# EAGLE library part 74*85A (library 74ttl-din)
4-bit Magnitude COMPARATOR
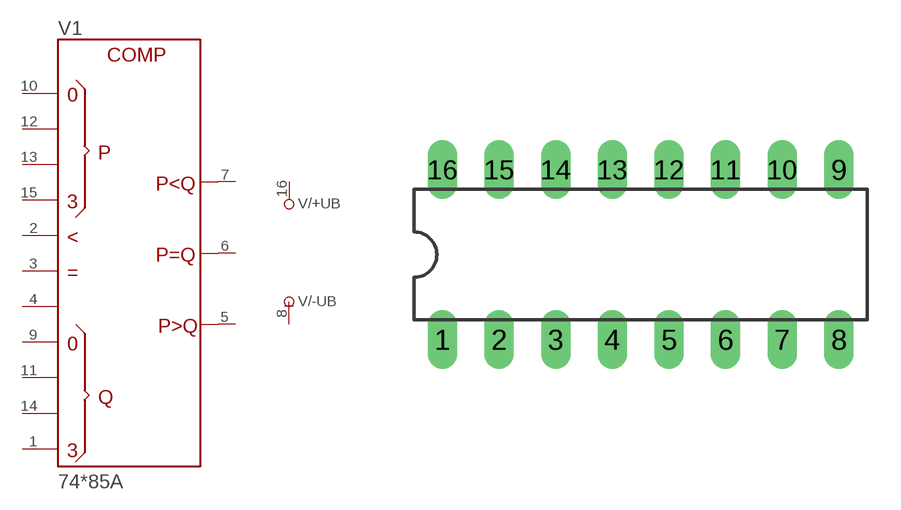
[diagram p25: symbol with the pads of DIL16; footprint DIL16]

Designator prefix V; gates /+UB=+UB /-UB=-UB 1=85A

## 7485AN  [DIL16]
1  1:Q3  in
2  1:PLTQ_  in
3  1:PEQQ_  in
4  1:PGTQ_  in
5  1:PGTQ  out
6  1:PEQQ  out
7  1:PLTQ  out
8  /-UB:-UB  pwr
9  1:Q0  in
10  1:P0  in
11  1:Q1  in
12  1:P1  in
13  1:P2  in
14  1:Q2  in
15  1:P3  in
16  /+UB:+UB  pwr

## Footprint DIL16 (pad centres in mm)
Dual In Line Package
drill 0.813 long: 1 -8.89,-3.81; 2 -6.35,-3.81; 3 -3.81,-3.81; 4 -1.27,-3.81; 5 1.27,-3.81; 6 3.81,-3.81; 7 6.35,-3.81; 8 8.89,-3.81; 9 8.89,3.81; 10 6.35,3.81; 11 3.81,3.81; 12 1.27,3.81; 13 -1.27,3.81; 14 -3.81,3.81; 15 -6.35,3.81; 16 -8.89,3.81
